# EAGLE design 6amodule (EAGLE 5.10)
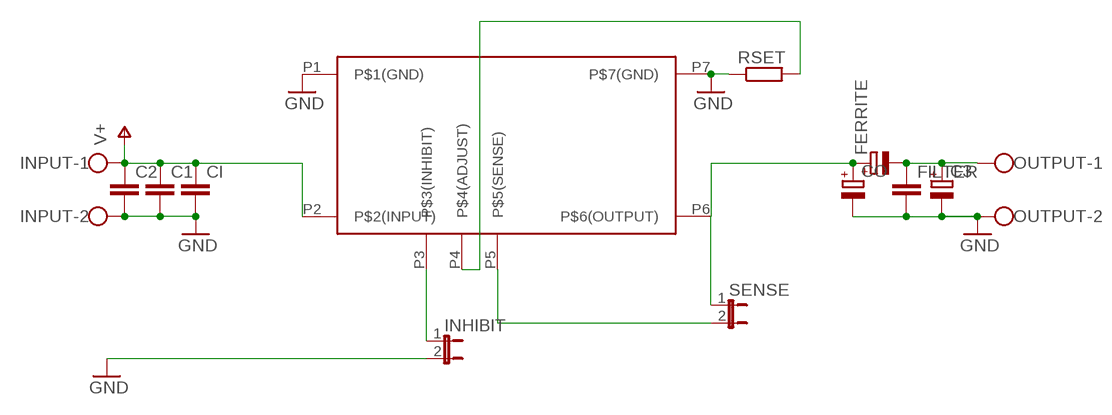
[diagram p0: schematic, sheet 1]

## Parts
C1  C-EUC1206  [C1206]
C2  C-EUC1206  [C1206]
C3  CPOL-EUE2.5-6  [E2,5-6]
CI  C-EUC1206  [C1206]
CO  CPOL-EUE5-10.5  [E5-10,5]
FERRITE  CPOL-EUE2.5-5  [E2,5-5]
FILTER  C-EUC1206  [C1206]
INHIBIT  JP1E  [JP1]
INPUT  W237-102  [W237-102]
OUTPUT  W237-102  [W237-102]
RSET  R-EU_0207/10  [0207/10]
SENSE  JP1E  [JP1]
U$1  6APOWERMODULE  [6APOWERMODULE]

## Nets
GND: C1.2 C2.2 C3.- CI.2 CO.- FILTER.2 INHIBIT.2 INPUT.2 OUTPUT.2 RSET.1 U$1.P1(P$1(GND)) U$1.P7(P$7(GND))
N$1: SENSE.2 U$1.P5(P$5(SENSE))
N$3: INHIBIT.1 U$1.P3(P$3(INHIBIT))
N$4: CO.+ FERRITE.+ SENSE.1 U$1.P6(P$6(OUTPUT))
N$5: RSET.2 U$1.P4(P$4(ADJUST))
N$6: C3.+ FERRITE.- FILTER.1 OUTPUT.1
V+: C1.1 C2.1 CI.1 INPUT.1 U$1.P2(P$2(INPUT))

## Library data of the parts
C1 C2 CI FILTER = rcl:C-EU: CAPACITOR, European symbol
C3 CO FERRITE = rcl:CPOL-EU: POLARIZED CAPACITOR, European symbol
INHIBIT SENSE = jumper:JP1E: JUMPER
INPUT OUTPUT = con-wago-500:W237-102: WAGO SCREW CLAMP
RSET = rcl:R-EU_: RESISTOR, European symbol
U$1 = TIPOWERMODULE:6APOWERMODULE

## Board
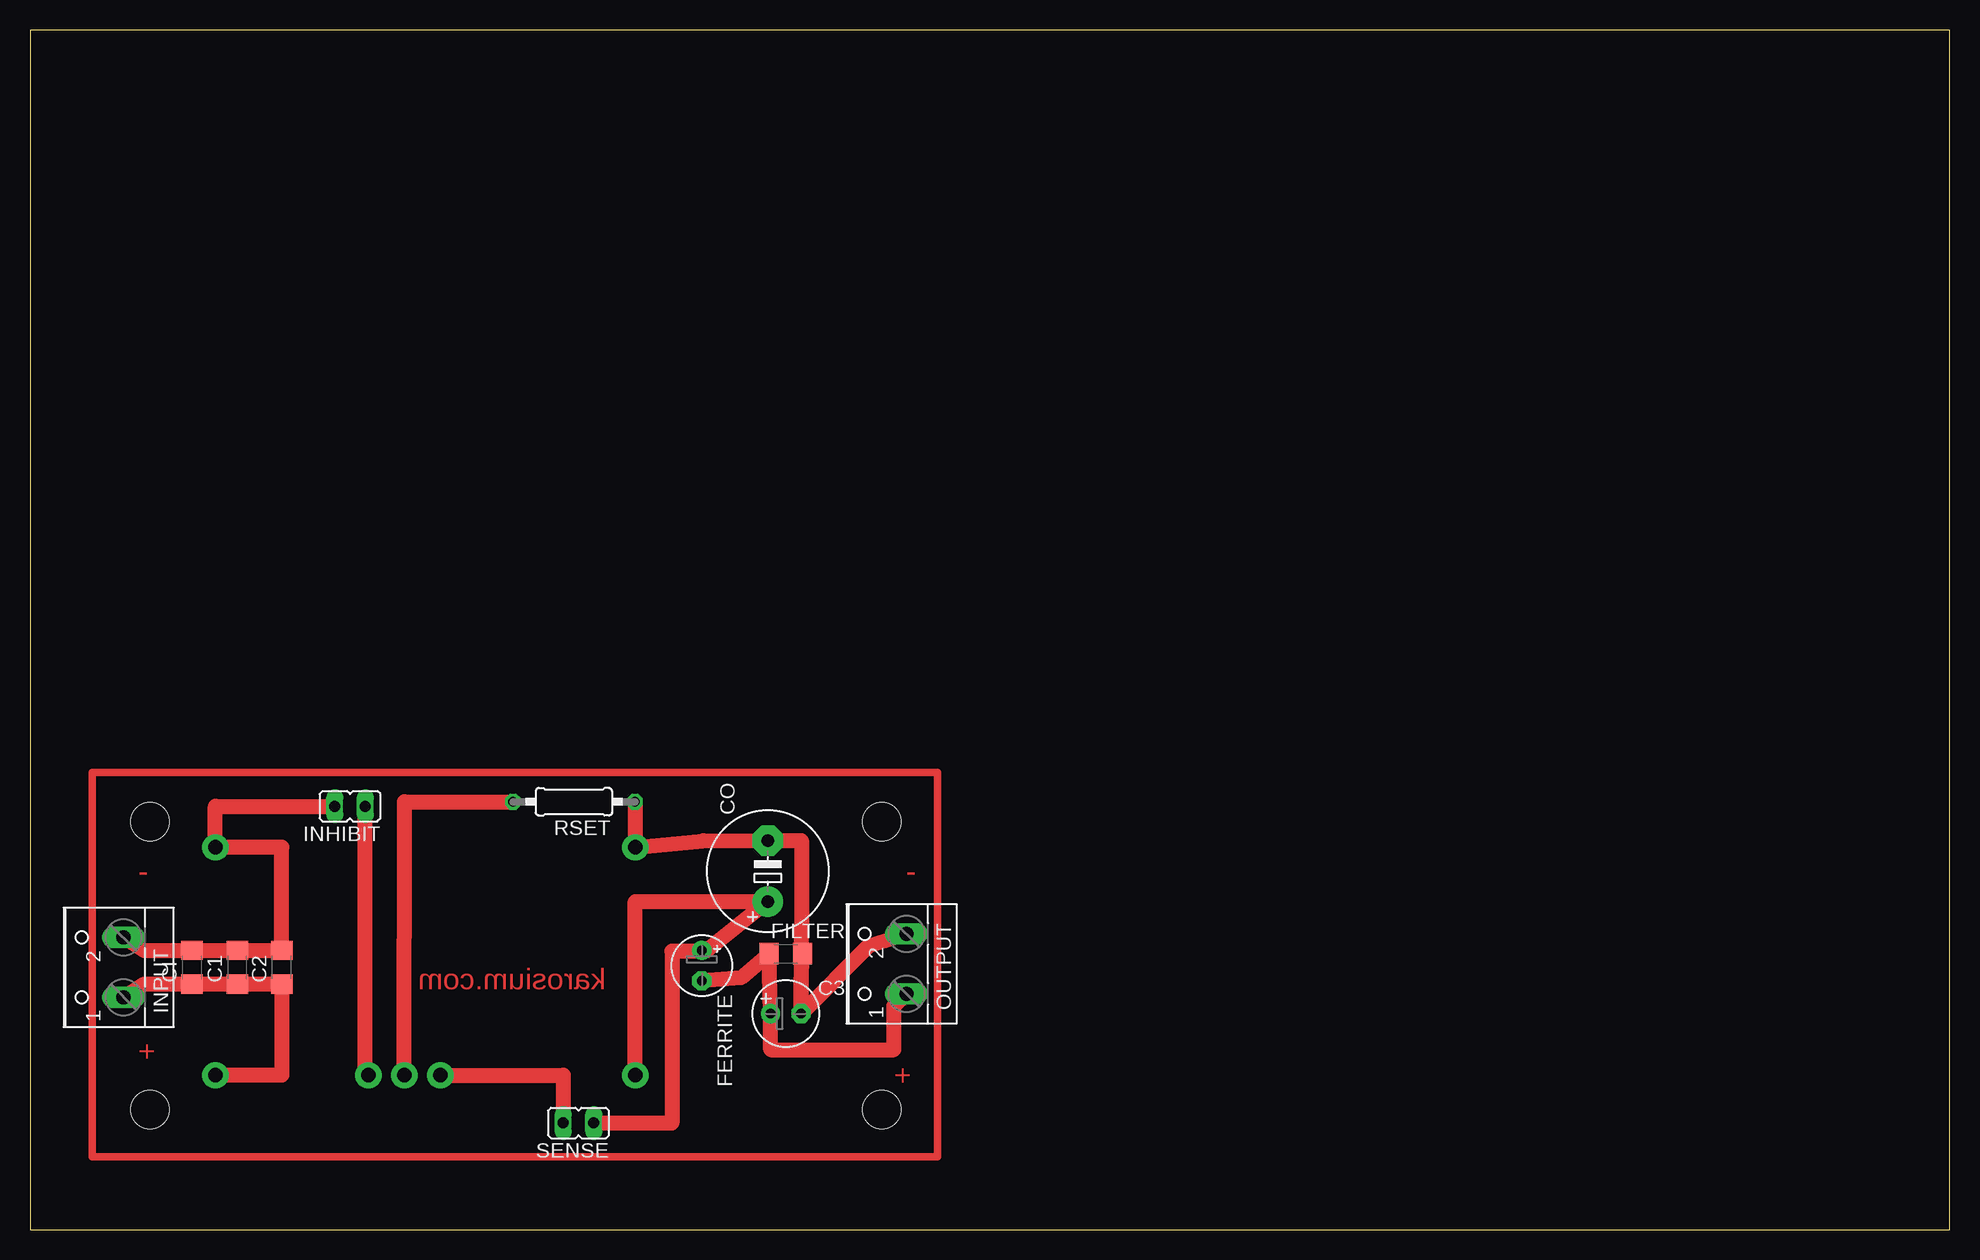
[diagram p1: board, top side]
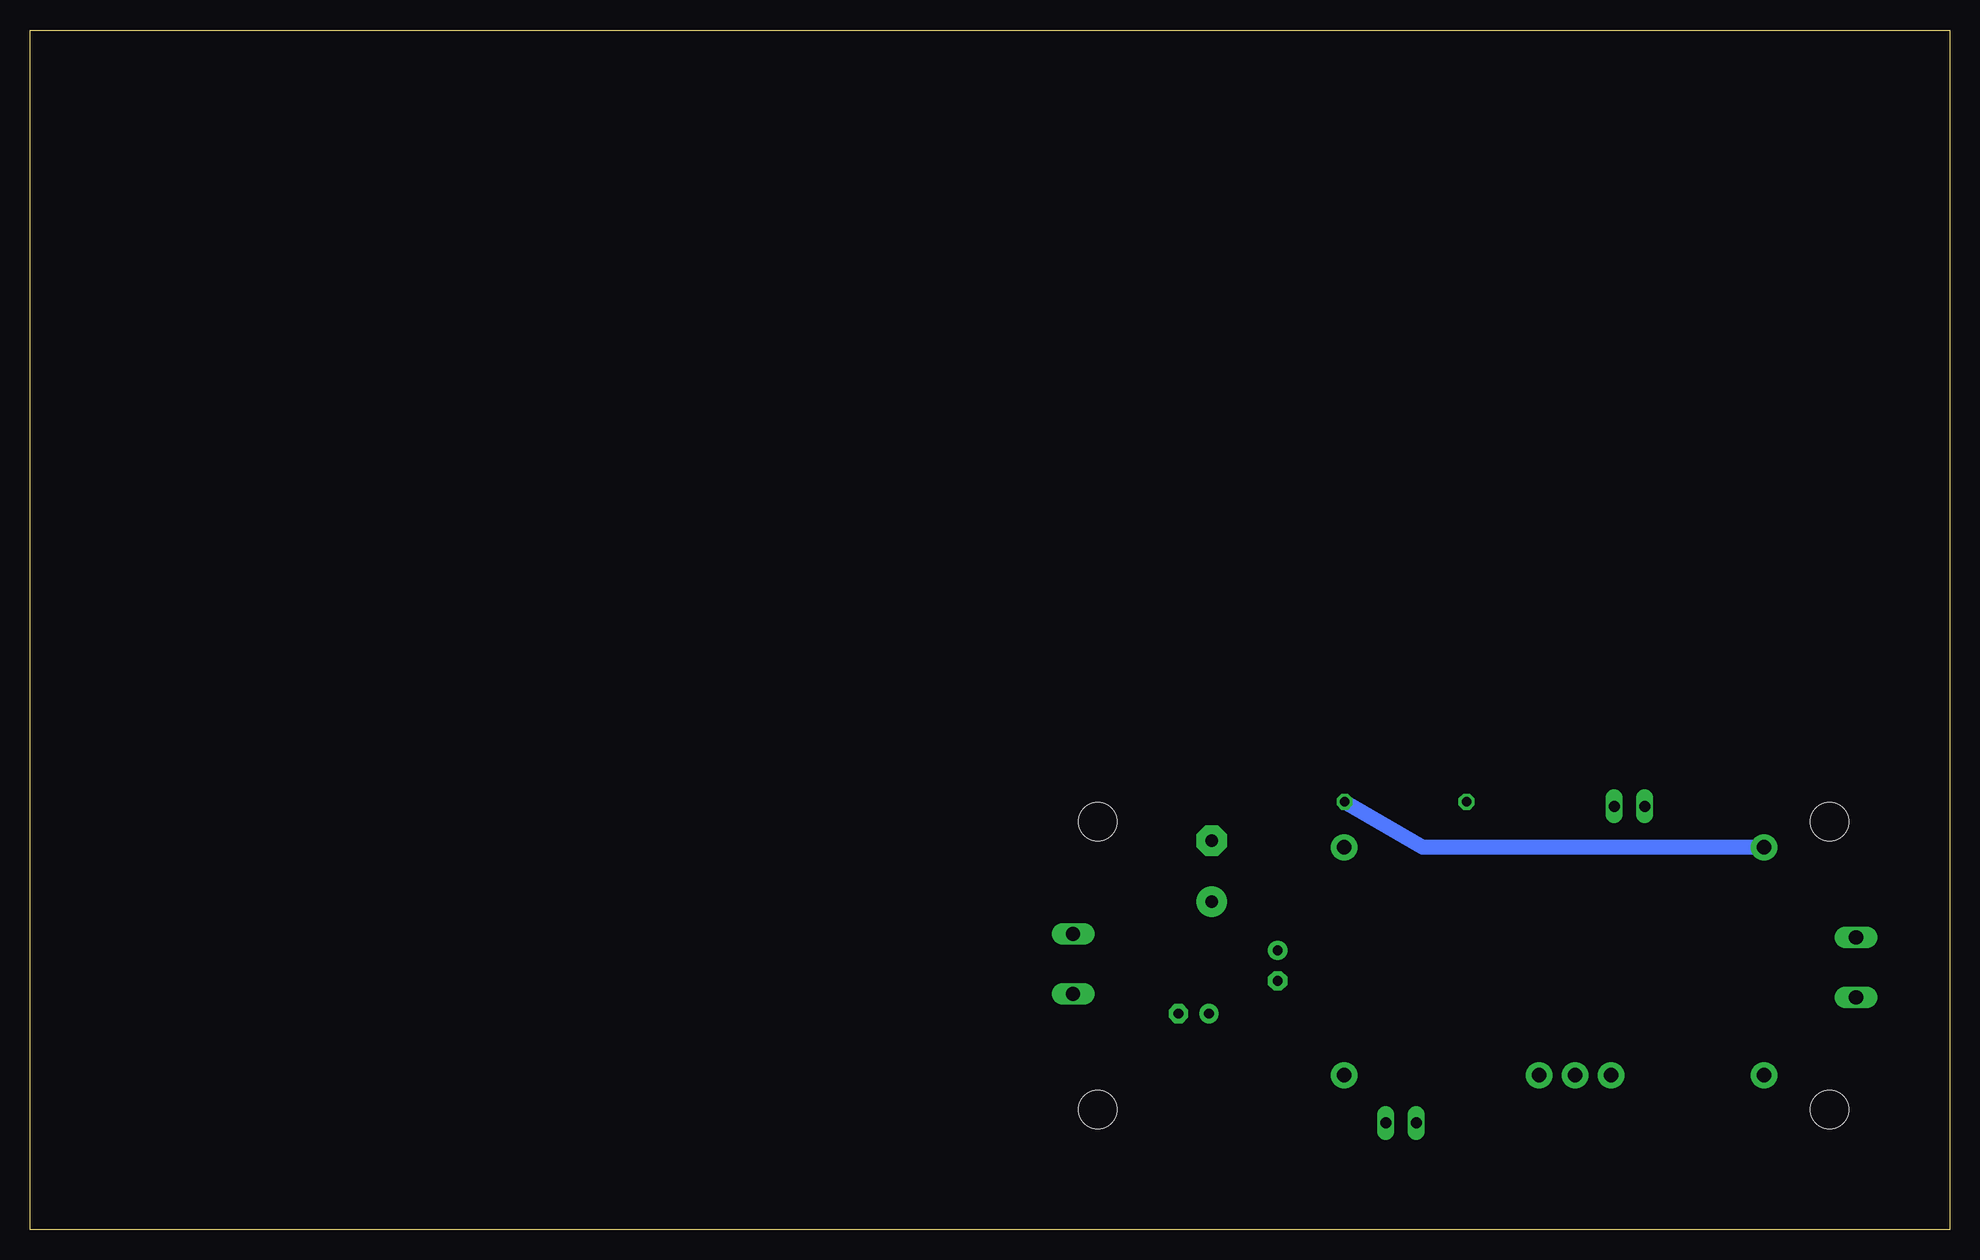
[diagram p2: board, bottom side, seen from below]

Size 160 x 100 mm. Coordinates in mm from the lower left corner, seen from the top.
Outline: 0,0 160,0 160,100 0,100 0,0
Copper layers (1*16): Top 0.035mm / dielectric 1.5mm / Bottom 0.035mm
Design rules "default": minimum track width 10mil, minimum drill 24mil, track to track 8mil, track to pad 8mil, pad to pad 8mil, via to via 8mil, smd to smd 8mil, copper to edge 40mil, drill to drill 8mil, minimum pad ring 10mil, minimum via ring 8mil, stop-mask expansion 4mil, vias tented up to drill 0mil, thermal gap 10mil
Holes 3.2 mm at 10,10 71,10 10,34 71,34

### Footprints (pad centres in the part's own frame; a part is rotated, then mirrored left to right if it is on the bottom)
C1206 = smd 1.6 x 1.8: 1 -1.4,0; 2 1.4,0
E2,5-6 = drill 0.813 pad 1.6 round: + -1.27,0 | drill 0.813 pad 1.6 octagon: - 1.27,0
E5-10,5 = drill 1.016 pad 2.54 round: + -2.54,0 | drill 1.016 pad 2.54 octagon: - 2.54,0
E2,5-5 = drill 0.813 pad 1.6 round: + -1.27,0 | drill 0.813 pad 1.6 octagon: - 1.27,0
JP1 = drill 0.914 long: 1 0,-1.27; 2 0,1.27
W237-102 = drill 1.194 long: 1 -2.5,-1.27; 2 2.5,-1.27
0207/10 = drill 0.813 octagon: 1 -5.08,0; 2 5.08,0
6APOWERMODULE = drill 1.2 pad 2.184 round: P1 25,-9; P2 25,10; P3 12.25,10; P4 9.25,10; P5 6.25,10; P6 -10,10; P7 -10,-9

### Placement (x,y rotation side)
C1  17.29,21.86 90 top
C2  20.99,21.86 90 top
C3  63,18 0 top
CI  13.51,21.86 90 top
CO  61.5,29.88 90 top
FERRITE  56,22 270 top
FILTER  63,23 0 top
INHIBIT  26.67,35.29 90 top
INPUT  6.53,21.86 90 top
OUTPUT  71.79,22.14 90 top
RSET  45.34,35.66 180 top
SENSE  45.72,8.89 90 top
U$1  40.45,22.86 180 top

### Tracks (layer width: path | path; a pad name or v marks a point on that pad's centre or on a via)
GND
  Top 1.27: RSET.1 U$1.P7 56.11,32.41 CO.- 64.31,32.42 C3.- | INHIBIT.2 15.45,35.29 U$1.P1 20.99,31.86 C2.2 C1.2 CI.2 9.54,23.26 INPUT.2 | C3.- 64.27,20.6 FILTER.2 | OUTPUT.2 69.91,23.64 C3.-
  Bottom 1.27: RSET.1 43.91,31.86 U$1.P1
N$1
  Top 1.27: SENSE.2 44.45,12.86 U$1.P5
N$2
  Top 0.61: 5.17,38.1 75.63,38.1 75.63,6.08 5.17,6.08 5.17,38.1
N$3
  Top 1.27: INHIBIT.1 27.94,12.86 U$1.P3
N$4
  Top 1.27: U$1.P6 50.45,27.34 CO.+ 56.45,23.27 FERRITE.+ 56,23.2 53.5,23.2 53.5,8.89 SENSE.1
N$5
  Top 1.27: RSET.2 31.22,35.66 U$1.P4
N$6
  Top 1.27: FERRITE.- 59.27,21 FILTER.1 C3.+ 61.73,15 72,15 72,18.64 OUTPUT.1
V+
  Top 1.27: U$1.P2 20.99,12.86 C2.1 C1.1 CI.1 9.54,20.46 INPUT.1

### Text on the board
Top: - | - | karosium.com | + | +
